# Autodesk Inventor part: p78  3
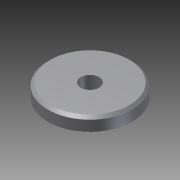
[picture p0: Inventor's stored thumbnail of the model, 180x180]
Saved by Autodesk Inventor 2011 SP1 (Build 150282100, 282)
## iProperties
Created: 2014-02
Part Number: p78  3
Document SubType Name: Modeling
Designer: Administrator
Density: 1 g/cm^3
Author: Administrator
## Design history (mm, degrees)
sketch "草图1"
  geometry: C1 r 16 at (0, 0); 1 further point
  constraints: 1 centre point, 1 coincident
  dimensions: "d0" = 32 diameter of C1
extrude "拉伸1" new body sketch "草图1" distance "d1" = 5; taper "d2" = 0 deg
chamfer "倒角1" distance "d3" = 1; stored, may be unused: second distance "d4" = 2, angle "d5" = 45 deg
hole "Hole1" diameter "d8" = 7; stored, may be unused: countersink angle "d12" = 90 deg, drill point angle "d14" = 118 deg; dims "d6" = 10, "d7" = 10, "d9" = 6, "d10" = 4, "d11" = 2, "d13" = 8
node "实体1"
